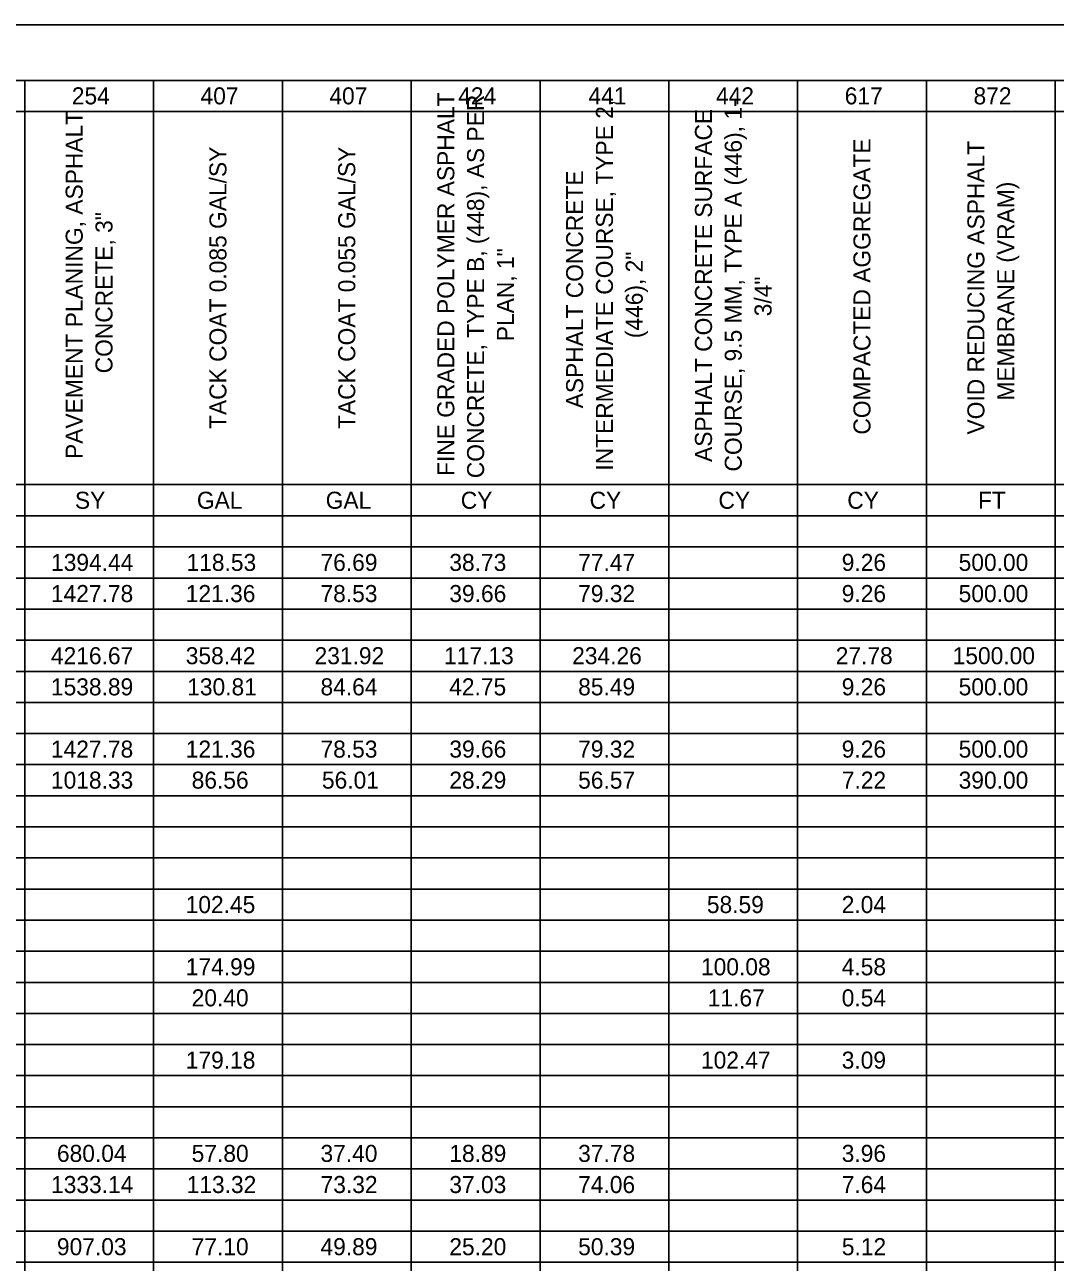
# Model space of a CAD drawing. Extents: x 0 to 34, y 0 to 22.
# Drawn here: x 16.38 to 25.65, y 10.87 to 22 of the extents above; entities that cross this region are included whole.
import ezdxf

# ---------------------------------------------------------------- set-up
doc = ezdxf.new("R2010")
doc.units = 0
for name, color, linetype in [('SH_Border', 7, 'Continuous'), ('SH_Cut_Line', 7, 'Continuous'), ('SH_Text', 7, 'Continuous')]:
    doc.layers.add(name, color=color, linetype=linetype)

msp = doc.modelspace()

# ---------------------------------------------------------------- linework, layer by layer
at = {"layer": 'SH_Border'}
msp.add_lwpolyline([(1.5, 21.5), (33.5, 21.5), (33.5, 0.5), (1.5, 0.5)], close=True, dxfattribs=at)
at = {"layer": 'SH_Cut_Line'}
msp.add_lwpolyline([(0, 0), (34, 0), (34, 22), (0, 22)], close=True, dxfattribs=at)
at = {"layer": 'SH_Text'}
for p, q in [((15.22, 21.5), (16.378, 21.5)), ((16.378, 21.5), (24.49, 21.5)), ((16.378, 21.5), (16.378, 21.22)), ((17.537, 21.5), (17.537, 21.22)), ((18.696, 21.5), (18.696, 21.22)), ((19.855, 21.5), (19.855, 21.22)), ((21.014, 21.5), (21.014, 21.22)), ((22.173, 21.5), (22.173, 21.22)), ((23.331, 21.5), (23.331, 21.22)), ((24.49, 21.5), (25.649, 21.5)), ((24.49, 21.5), (24.49, 21.22)), ((25.649, 21.5), (27.967, 21.5)), ((25.649, 21.5), (25.649, 21.22)), ((15.22, 21.22), (16.378, 21.22)), ((16.378, 21.22), (24.49, 21.22)), ((16.378, 21.22), (16.378, 20.941)), ((17.537, 21.22), (17.537, 20.941)), ((18.696, 21.22), (18.696, 20.941)), ((19.855, 21.22), (19.855, 20.941)), ((21.014, 21.22), (21.014, 20.941)), ((22.173, 21.22), (22.173, 20.941)), ((23.331, 21.22), (23.331, 20.941)), ((24.49, 21.22), (25.649, 21.22)), ((24.49, 21.22), (24.49, 20.941)), ((25.649, 21.22), (27.967, 21.22)), ((25.649, 21.22), (25.649, 20.941)), ((16.378, 20.941), (16.378, 20.661)), ((17.537, 20.941), (17.537, 20.661)), ((18.696, 20.941), (18.696, 20.661)), ((19.855, 20.941), (19.855, 20.661)), ((21.014, 20.941), (21.014, 20.661)), ((22.173, 20.941), (22.173, 20.661)), ((23.331, 20.941), (23.331, 20.661)), ((24.49, 20.941), (24.49, 20.661)), ((25.649, 20.941), (25.649, 20.661)), ((16.378, 20.661), (16.378, 20.381)), ((17.537, 20.661), (17.537, 20.381)), ((18.696, 20.661), (18.696, 20.381)), ((19.855, 20.661), (19.855, 20.381)), ((21.014, 20.661), (21.014, 20.381)), ((22.173, 20.661), (22.173, 20.381)), ((23.331, 20.661), (23.331, 20.381)), ((24.49, 20.661), (24.49, 20.381)), ((25.649, 20.661), (25.649, 20.381)), ((16.378, 20.381), (16.378, 20.101)), ((17.537, 20.381), (17.537, 20.101)), ((18.696, 20.381), (18.696, 20.101)), ((19.855, 20.381), (19.855, 20.101)), ((21.014, 20.381), (21.014, 20.101)), ((22.173, 20.381), (22.173, 20.101)), ((23.331, 20.381), (23.331, 20.101)), ((24.49, 20.381), (24.49, 20.101)), ((25.649, 20.381), (25.649, 20.101)), ((16.378, 20.101), (16.378, 19.822)), ((17.537, 20.101), (17.537, 19.822)), ((18.696, 20.101), (18.696, 19.822)), ((19.855, 20.101), (19.855, 19.822)), ((21.014, 20.101), (21.014, 19.822)), ((22.173, 20.101), (22.173, 19.822)), ((23.331, 20.101), (23.331, 19.822)), ((24.49, 20.101), (24.49, 19.822)), ((25.649, 20.101), (25.649, 19.822)), ((16.378, 19.822), (16.378, 19.542)), ((17.537, 19.822), (17.537, 19.542)), ((18.696, 19.822), (18.696, 19.542)), ((19.855, 19.822), (19.855, 19.542)), ((21.014, 19.822), (21.014, 19.542)), ((22.173, 19.822), (22.173, 19.542)), ((23.331, 19.822), (23.331, 19.542)), ((24.49, 19.822), (24.49, 19.542)), ((25.649, 19.822), (25.649, 19.542)), ((16.378, 19.542), (16.378, 19.262)), ((17.537, 19.542), (17.537, 19.262)), ((18.696, 19.542), (18.696, 19.262)), ((19.855, 19.542), (19.855, 19.262)), ((21.014, 19.542), (21.014, 19.262)), ((22.173, 19.542), (22.173, 19.262)), ((23.331, 19.542), (23.331, 19.262)), ((24.49, 19.542), (24.49, 19.262)), ((25.649, 19.542), (25.649, 19.262)), ((16.378, 19.262), (16.378, 18.983)), ((17.537, 19.262), (17.537, 18.983)), ((18.696, 19.262), (18.696, 18.983)), ((19.855, 19.262), (19.855, 18.983)), ((21.014, 19.262), (21.014, 18.983)), ((22.173, 19.262), (22.173, 18.983)), ((23.331, 19.262), (23.331, 18.983)), ((24.49, 19.262), (24.49, 18.983)), ((25.649, 19.262), (25.649, 18.983)), ((16.378, 18.983), (16.378, 18.703)), ((17.537, 18.983), (17.537, 18.703)), ((18.696, 18.983), (18.696, 18.703)), ((19.855, 18.983), (19.855, 18.703)), ((21.014, 18.983), (21.014, 18.703)), ((22.173, 18.983), (22.173, 18.703)), ((23.331, 18.983), (23.331, 18.703)), ((24.49, 18.983), (24.49, 18.703)), ((25.649, 18.983), (25.649, 18.703)), ((16.378, 18.703), (16.378, 18.423)), ((17.537, 18.703), (17.537, 18.423)), ((18.696, 18.703), (18.696, 18.423)), ((19.855, 18.703), (19.855, 18.423)), ((21.014, 18.703), (21.014, 18.423)), ((22.173, 18.703), (22.173, 18.423)), ((23.331, 18.703), (23.331, 18.423)), ((24.49, 18.703), (24.49, 18.423)), ((25.649, 18.703), (25.649, 18.423)), ((16.378, 18.423), (16.378, 18.143)), ((17.537, 18.423), (17.537, 18.143)), ((18.696, 18.423), (18.696, 18.143)), ((19.855, 18.423), (19.855, 18.143)), ((21.014, 18.423), (21.014, 18.143)), ((22.173, 18.423), (22.173, 18.143)), ((23.331, 18.423), (23.331, 18.143)), ((24.49, 18.423), (24.49, 18.143)), ((25.649, 18.423), (25.649, 18.143)), ((16.378, 18.143), (16.378, 17.864)), ((17.537, 18.143), (17.537, 17.864)), ((18.696, 18.143), (18.696, 17.864)), ((19.855, 18.143), (19.855, 17.864)), ((21.014, 18.143), (21.014, 17.864)), ((22.173, 18.143), (22.173, 17.864)), ((23.331, 18.143), (23.331, 17.864)), ((24.49, 18.143), (24.49, 17.864)), ((25.649, 18.143), (25.649, 17.864)), ((15.22, 17.864), (16.378, 17.864)), ((16.378, 17.864), (24.49, 17.864)), ((16.378, 17.864), (16.378, 17.584)), ((17.537, 17.864), (17.537, 17.584)), ((18.696, 17.864), (18.696, 17.584)), ((19.855, 17.864), (19.855, 17.584)), ((21.014, 17.864), (21.014, 17.584)), ((22.173, 17.864), (22.173, 17.584)), ((23.331, 17.864), (23.331, 17.584)), ((24.49, 17.864), (25.649, 17.864)), ((24.49, 17.864), (24.49, 17.584)), ((25.649, 17.864), (27.967, 17.864)), ((25.649, 17.864), (25.649, 17.584)), ((15.22, 17.584), (16.378, 17.584)), ((16.378, 17.584), (24.49, 17.584)), ((16.378, 17.584), (16.378, 17.304)), ((17.537, 17.584), (17.537, 17.304)), ((18.696, 17.584), (18.696, 17.304)), ((19.855, 17.584), (19.855, 17.304)), ((21.014, 17.584), (21.014, 17.304)), ((22.173, 17.584), (22.173, 17.304)), ((23.331, 17.584), (23.331, 17.304)), ((24.49, 17.584), (25.649, 17.584)), ((24.49, 17.584), (24.49, 17.304)), ((25.649, 17.584), (27.967, 17.584)), ((25.649, 17.584), (25.649, 17.304)), ((15.22, 17.304), (16.378, 17.304)), ((16.378, 17.304), (24.49, 17.304)), ((16.378, 17.304), (16.378, 17.024)), ((17.537, 17.304), (17.537, 17.024)), ((18.696, 17.304), (18.696, 17.024)), ((19.855, 17.304), (19.855, 17.024)), ((21.014, 17.304), (21.014, 17.024)), ((22.173, 17.304), (22.173, 17.024)), ((23.331, 17.304), (23.331, 17.024)), ((24.49, 17.304), (25.649, 17.304)), ((24.49, 17.304), (24.49, 17.024)), ((25.649, 17.304), (27.967, 17.304)), ((25.649, 17.304), (25.649, 17.024)), ((15.22, 17.024), (16.378, 17.024)), ((16.378, 17.024), (24.49, 17.024)), ((16.378, 17.024), (16.378, 16.745)), ((17.537, 17.024), (17.537, 16.745)), ((18.696, 17.024), (18.696, 16.745)), ((19.855, 17.024), (19.855, 16.745)), ((21.014, 17.024), (21.014, 16.745)), ((22.173, 17.024), (22.173, 16.745)), ((23.331, 17.024), (23.331, 16.745)), ((24.49, 17.024), (25.649, 17.024)), ((24.49, 17.024), (24.49, 16.745)), ((25.649, 17.024), (27.967, 17.024)), ((25.649, 17.024), (25.649, 16.745)), ((15.22, 16.745), (16.378, 16.745)), ((16.378, 16.745), (24.49, 16.745)), ((16.378, 16.745), (16.378, 16.465)), ((17.537, 16.745), (17.537, 16.465)), ((18.696, 16.745), (18.696, 16.465)), ((19.855, 16.745), (19.855, 16.465)), ((21.014, 16.745), (21.014, 16.465)), ((22.173, 16.745), (22.173, 16.465)), ((23.331, 16.745), (23.331, 16.465)), ((24.49, 16.745), (25.649, 16.745)), ((24.49, 16.745), (24.49, 16.465)), ((25.649, 16.745), (27.967, 16.745)), ((25.649, 16.745), (25.649, 16.465)), ((15.22, 16.465), (16.378, 16.465)), ((16.378, 16.465), (24.49, 16.465)), ((16.378, 16.465), (16.378, 16.185)), ((17.537, 16.465), (17.537, 16.185)), ((18.696, 16.465), (18.696, 16.185)), ((19.855, 16.465), (19.855, 16.185)), ((21.014, 16.465), (21.014, 16.185)), ((22.173, 16.465), (22.173, 16.185)), ((23.331, 16.465), (23.331, 16.185)), ((24.49, 16.465), (25.649, 16.465)), ((24.49, 16.465), (24.49, 16.185)), ((25.649, 16.465), (27.967, 16.465)), ((25.649, 16.465), (25.649, 16.185)), ((15.22, 16.185), (16.378, 16.185)), ((16.378, 16.185), (24.49, 16.185)), ((16.378, 16.185), (16.378, 15.906)), ((17.537, 16.185), (17.537, 15.906)), ((18.696, 16.185), (18.696, 15.906)), ((19.855, 16.185), (19.855, 15.906)), ((21.014, 16.185), (21.014, 15.906)), ((22.173, 16.185), (22.173, 15.906)), ((23.331, 16.185), (23.331, 15.906)), ((24.49, 16.185), (25.649, 16.185)), ((24.49, 16.185), (24.49, 15.906)), ((25.649, 16.185), (27.967, 16.185)), ((25.649, 16.185), (25.649, 15.906)), ((15.22, 15.906), (16.378, 15.906)), ((16.378, 15.906), (24.49, 15.906)), ((16.378, 15.906), (16.378, 15.626)), ((17.537, 15.906), (17.537, 15.626)), ((18.696, 15.906), (18.696, 15.626)), ((19.855, 15.906), (19.855, 15.626)), ((21.014, 15.906), (21.014, 15.626)), ((22.173, 15.906), (22.173, 15.626)), ((23.331, 15.906), (23.331, 15.626)), ((24.49, 15.906), (25.649, 15.906)), ((24.49, 15.906), (24.49, 15.626)), ((25.649, 15.906), (27.967, 15.906)), ((25.649, 15.906), (25.649, 15.626)), ((15.22, 15.626), (16.378, 15.626)), ((16.378, 15.626), (24.49, 15.626)), ((16.378, 15.626), (16.378, 15.346)), ((17.537, 15.626), (17.537, 15.346)), ((18.696, 15.626), (18.696, 15.346)), ((19.855, 15.626), (19.855, 15.346)), ((21.014, 15.626), (21.014, 15.346)), ((22.173, 15.626), (22.173, 15.346)), ((23.331, 15.626), (23.331, 15.346)), ((24.49, 15.626), (25.649, 15.626)), ((24.49, 15.626), (24.49, 15.346)), ((25.649, 15.626), (27.967, 15.626)), ((25.649, 15.626), (25.649, 15.346)), ((15.22, 15.346), (16.378, 15.346)), ((16.378, 15.346), (24.49, 15.346)), ((16.378, 15.346), (16.378, 15.066)), ((17.537, 15.346), (17.537, 15.066)), ((18.696, 15.346), (18.696, 15.066)), ((19.855, 15.346), (19.855, 15.066)), ((21.014, 15.346), (21.014, 15.066)), ((22.173, 15.346), (22.173, 15.066)), ((23.331, 15.346), (23.331, 15.066)), ((24.49, 15.346), (25.649, 15.346)), ((24.49, 15.346), (24.49, 15.066)), ((25.649, 15.346), (27.967, 15.346)), ((25.649, 15.346), (25.649, 15.066)), ((15.22, 15.066), (16.378, 15.066)), ((16.378, 15.066), (24.49, 15.066)), ((16.378, 15.066), (16.378, 14.787)), ((17.537, 15.066), (17.537, 14.787)), ((18.696, 15.066), (18.696, 14.787)), ((19.855, 15.066), (19.855, 14.787)), ((21.014, 15.066), (21.014, 14.787)), ((22.173, 15.066), (22.173, 14.787)), ((23.331, 15.066), (23.331, 14.787)), ((24.49, 15.066), (25.649, 15.066)), ((24.49, 15.066), (24.49, 14.787)), ((25.649, 15.066), (27.967, 15.066)), ((25.649, 15.066), (25.649, 14.787)), ((15.22, 14.787), (16.378, 14.787)), ((16.378, 14.787), (24.49, 14.787)), ((16.378, 14.787), (16.378, 14.507)), ((17.537, 14.787), (17.537, 14.507)), ((18.696, 14.787), (18.696, 14.507)), ((19.855, 14.787), (19.855, 14.507)), ((21.014, 14.787), (21.014, 14.507)), ((22.173, 14.787), (22.173, 14.507)), ((23.331, 14.787), (23.331, 14.507)), ((24.49, 14.787), (25.649, 14.787)), ((24.49, 14.787), (24.49, 14.507)), ((25.649, 14.787), (27.967, 14.787)), ((25.649, 14.787), (25.649, 14.507)), ((15.22, 14.507), (16.378, 14.507)), ((16.378, 14.507), (24.49, 14.507)), ((16.378, 14.507), (16.378, 14.227)), ((17.537, 14.507), (17.537, 14.227)), ((18.696, 14.507), (18.696, 14.227)), ((19.855, 14.507), (19.855, 14.227)), ((21.014, 14.507), (21.014, 14.227)), ((22.173, 14.507), (22.173, 14.227)), ((23.331, 14.507), (23.331, 14.227)), ((24.49, 14.507), (25.649, 14.507)), ((24.49, 14.507), (24.49, 14.227)), ((25.649, 14.507), (27.967, 14.507)), ((25.649, 14.507), (25.649, 14.227)), ((15.22, 14.227), (16.378, 14.227)), ((16.378, 14.227), (24.49, 14.227)), ((16.378, 14.227), (16.378, 13.948)), ((17.537, 14.227), (17.537, 13.948)), ((18.696, 14.227), (18.696, 13.948)), ((19.855, 14.227), (19.855, 13.948)), ((21.014, 14.227), (21.014, 13.948)), ((22.173, 14.227), (22.173, 13.948)), ((23.331, 14.227), (23.331, 13.948)), ((24.49, 14.227), (25.649, 14.227)), ((24.49, 14.227), (24.49, 13.948)), ((25.649, 14.227), (27.967, 14.227)), ((25.649, 14.227), (25.649, 13.948)), ((15.22, 13.948), (16.378, 13.948)), ((16.378, 13.948), (24.49, 13.948)), ((16.378, 13.948), (16.378, 13.668)), ((17.537, 13.948), (17.537, 13.668)), ((18.696, 13.948), (18.696, 13.668)), ((19.855, 13.948), (19.855, 13.668)), ((21.014, 13.948), (21.014, 13.668)), ((22.173, 13.948), (22.173, 13.668)), ((23.331, 13.948), (23.331, 13.668)), ((24.49, 13.948), (25.649, 13.948)), ((24.49, 13.948), (24.49, 13.668)), ((25.649, 13.948), (27.967, 13.948)), ((25.649, 13.948), (25.649, 13.668)), ((15.22, 13.668), (16.378, 13.668)), ((16.378, 13.668), (24.49, 13.668)), ((16.378, 13.668), (16.378, 13.388)), ((17.537, 13.668), (17.537, 13.388)), ((18.696, 13.668), (18.696, 13.388)), ((19.855, 13.668), (19.855, 13.388)), ((21.014, 13.668), (21.014, 13.388)), ((22.173, 13.668), (22.173, 13.388)), ((23.331, 13.668), (23.331, 13.388)), ((24.49, 13.668), (25.649, 13.668)), ((24.49, 13.668), (24.49, 13.388)), ((25.649, 13.668), (27.967, 13.668)), ((25.649, 13.668), (25.649, 13.388)), ((15.22, 13.388), (16.378, 13.388)), ((16.378, 13.388), (24.49, 13.388)), ((16.378, 13.388), (16.378, 13.108)), ((17.537, 13.388), (17.537, 13.108)), ((18.696, 13.388), (18.696, 13.108)), ((19.855, 13.388), (19.855, 13.108)), ((21.014, 13.388), (21.014, 13.108)), ((22.173, 13.388), (22.173, 13.108)), ((23.331, 13.388), (23.331, 13.108)), ((24.49, 13.388), (25.649, 13.388)), ((24.49, 13.388), (24.49, 13.108)), ((25.649, 13.388), (27.967, 13.388)), ((25.649, 13.388), (25.649, 13.108)), ((15.22, 13.108), (16.378, 13.108)), ((16.378, 13.108), (24.49, 13.108)), ((16.378, 13.108), (16.378, 12.829)), ((17.537, 13.108), (17.537, 12.829)), ((18.696, 13.108), (18.696, 12.829)), ((19.855, 13.108), (19.855, 12.829)), ((21.014, 13.108), (21.014, 12.829)), ((22.173, 13.108), (22.173, 12.829)), ((23.331, 13.108), (23.331, 12.829)), ((24.49, 13.108), (25.649, 13.108)), ((24.49, 13.108), (24.49, 12.829)), ((25.649, 13.108), (27.967, 13.108)), ((25.649, 13.108), (25.649, 12.829)), ((15.22, 12.829), (16.378, 12.829)), ((16.378, 12.829), (24.49, 12.829)), ((16.378, 12.829), (16.378, 12.549)), ((17.537, 12.829), (17.537, 12.549)), ((18.696, 12.829), (18.696, 12.549)), ((19.855, 12.829), (19.855, 12.549)), ((21.014, 12.829), (21.014, 12.549)), ((22.173, 12.829), (22.173, 12.549)), ((23.331, 12.829), (23.331, 12.549)), ((24.49, 12.829), (25.649, 12.829)), ((24.49, 12.829), (24.49, 12.549)), ((25.649, 12.829), (27.967, 12.829)), ((25.649, 12.829), (25.649, 12.549)), ((15.22, 12.549), (16.378, 12.549)), ((16.378, 12.549), (24.49, 12.549)), ((16.378, 12.549), (16.378, 12.269)), ((17.537, 12.549), (17.537, 12.269)), ((18.696, 12.549), (18.696, 12.269)), ((19.855, 12.549), (19.855, 12.269)), ((21.014, 12.549), (21.014, 12.269)), ((22.173, 12.549), (22.173, 12.269)), ((23.331, 12.549), (23.331, 12.269)), ((24.49, 12.549), (25.649, 12.549)), ((24.49, 12.549), (24.49, 12.269)), ((25.649, 12.549), (27.967, 12.549)), ((25.649, 12.549), (25.649, 12.269)), ((15.22, 12.269), (16.378, 12.269)), ((16.378, 12.269), (24.49, 12.269)), ((16.378, 12.269), (16.378, 11.99)), ((17.537, 12.269), (17.537, 11.99)), ((18.696, 12.269), (18.696, 11.99)), ((19.855, 12.269), (19.855, 11.99)), ((21.014, 12.269), (21.014, 11.99)), ((22.173, 12.269), (22.173, 11.99)), ((23.331, 12.269), (23.331, 11.99)), ((24.49, 12.269), (25.649, 12.269)), ((24.49, 12.269), (24.49, 11.99)), ((25.649, 12.269), (27.967, 12.269)), ((25.649, 12.269), (25.649, 11.99)), ((15.22, 11.99), (16.378, 11.99)), ((16.378, 11.99), (24.49, 11.99)), ((16.378, 11.99), (16.378, 11.71)), ((17.537, 11.99), (17.537, 11.71)), ((18.696, 11.99), (18.696, 11.71)), ((19.855, 11.99), (19.855, 11.71)), ((21.014, 11.99), (21.014, 11.71)), ((22.173, 11.99), (22.173, 11.71)), ((23.331, 11.99), (23.331, 11.71)), ((24.49, 11.99), (25.649, 11.99)), ((24.49, 11.99), (24.49, 11.71)), ((25.649, 11.99), (27.967, 11.99)), ((25.649, 11.99), (25.649, 11.71)), ((15.22, 11.71), (16.378, 11.71)), ((16.378, 11.71), (24.49, 11.71)), ((16.378, 11.71), (16.378, 11.43)), ((17.537, 11.71), (17.537, 11.43)), ((18.696, 11.71), (18.696, 11.43)), ((19.855, 11.71), (19.855, 11.43)), ((21.014, 11.71), (21.014, 11.43)), ((22.173, 11.71), (22.173, 11.43)), ((23.331, 11.71), (23.331, 11.43)), ((24.49, 11.71), (25.649, 11.71)), ((24.49, 11.71), (24.49, 11.43)), ((25.649, 11.71), (27.967, 11.71)), ((25.649, 11.71), (25.649, 11.43)), ((15.22, 11.43), (16.378, 11.43)), ((16.378, 11.43), (24.49, 11.43)), ((16.378, 11.43), (16.378, 11.15)), ((17.537, 11.43), (17.537, 11.15)), ((18.696, 11.43), (18.696, 11.15)), ((19.855, 11.43), (19.855, 11.15)), ((21.014, 11.43), (21.014, 11.15)), ((22.173, 11.43), (22.173, 11.15)), ((23.331, 11.43), (23.331, 11.15)), ((24.49, 11.43), (25.649, 11.43)), ((24.49, 11.43), (24.49, 11.15)), ((25.649, 11.43), (27.967, 11.43)), ((25.649, 11.43), (25.649, 11.15)), ((15.22, 11.15), (16.378, 11.15)), ((16.378, 11.15), (24.49, 11.15)), ((16.378, 11.15), (16.378, 10.871)), ((17.537, 11.15), (17.537, 10.871)), ((18.696, 11.15), (18.696, 10.871)), ((19.855, 11.15), (19.855, 10.871)), ((21.014, 11.15), (21.014, 10.871)), ((22.173, 11.15), (22.173, 10.871)), ((23.331, 11.15), (23.331, 10.871)), ((24.49, 11.15), (25.649, 11.15)), ((24.49, 11.15), (24.49, 10.871)), ((25.649, 11.15), (27.967, 11.15)), ((25.649, 11.15), (25.649, 10.871)), ((15.22, 10.871), (16.378, 10.871)), ((16.378, 10.871), (24.49, 10.871)), ((16.378, 10.871), (16.378, 10.591)), ((17.537, 10.871), (17.537, 10.591)), ((18.696, 10.871), (18.696, 10.591)), ((19.855, 10.871), (19.855, 10.591)), ((21.014, 10.871), (21.014, 10.591)), ((22.173, 10.871), (22.173, 10.591)), ((23.331, 10.871), (23.331, 10.591)), ((24.49, 10.871), (25.649, 10.871)), ((24.49, 10.871), (24.49, 10.591)), ((25.649, 10.871), (27.967, 10.871)), ((25.649, 10.871), (25.649, 10.591))]:
    msp.add_line(p, q, dxfattribs=at)

# ---------------------------------------------------------------- texts
for s, p in [('254', (16.802, 21.284)), ('407', (17.96, 21.284)), ('407', (19.119, 21.284)), ('424', (20.278, 21.284)), ('441', (21.45, 21.284)), ('442', (22.597, 21.284)), ('617', (23.755, 21.284)), ('872', (24.914, 21.284)), ('SY', (16.83, 17.647)), ('GAL', (17.927, 17.647)), ('GAL', (19.086, 17.647)), ('CY', (20.301, 17.647)), ('CY', (21.46, 17.647)), ('CY', (22.619, 17.647)), ('CY', (23.778, 17.647)), ('FT', (24.954, 17.647)), ('1394.44', (16.615, 17.088)), ('118.53', (17.834, 17.088)), ('76.69', (19.039, 17.088)), ('38.73', (20.198, 17.088)), ('77.47', (21.357, 17.088)), ('9.26', (23.728, 17.088)), ('500.00', (24.78, 17.088)), ('1427.78', (16.614, 16.808)), ('121.36', (17.827, 16.808)), ('78.53', (19.039, 16.808)), ('39.66', (20.198, 16.808)), ('79.32', (21.357, 16.808)), ('9.26', (23.728, 16.808)), ('500.00', (24.78, 16.808)), ('4216.67', (16.614, 16.249)), ('358.42', (17.827, 16.249)), ('231.92', (18.986, 16.249)), ('117.13', (20.151, 16.249)), ('234.26', (21.303, 16.249)), ('27.78', (23.674, 16.249)), ('1500.00', (24.726, 16.249)), ('1538.89', (16.614, 15.969)), ('130.81', (17.84, 15.969)), ('84.64', (19.039, 15.969)), ('42.75', (20.197, 15.969)), ('85.49', (21.357, 15.969)), ('9.26', (23.728, 15.969)), ('500.00', (24.78, 15.969)), ('1427.78', (16.614, 15.409)), ('121.36', (17.827, 15.409)), ('78.53', (19.039, 15.409)), ('39.66', (20.198, 15.409)), ('79.32', (21.357, 15.409)), ('9.26', (23.728, 15.409)), ('500.00', (24.78, 15.409)), ('1018.33', (16.614, 15.13)), ('86.56', (17.88, 15.13)), ('56.01', (19.052, 15.13)), ('28.29', (20.198, 15.13)), ('56.57', (21.357, 15.13)), ('7.22', (23.729, 15.13)), ('390.00', (24.78, 15.13)), ('102.45', (17.826, 14.011)), ('58.59', (22.515, 14.011)), ('2.04', (23.728, 14.011)), ('174.99', (17.827, 13.451)), ('100.08', (22.462, 13.451)), ('4.58', (23.728, 13.451)), ('20.40', (17.88, 13.172)), ('11.67', (22.523, 13.172)), ('0.54', (23.728, 13.172)), ('179.18', (17.827, 12.612)), ('102.47', (22.462, 12.612)), ('3.09', (23.728, 12.612)), ('680.04', (16.668, 11.773)), ('57.80', (17.88, 11.773)), ('37.40', (19.039, 11.773)), ('18.89', (20.198, 11.773)), ('37.78', (21.357, 11.773)), ('3.96', (23.728, 11.773)), ('1333.14', (16.615, 11.493)), ('113.32', (17.835, 11.493)), ('73.32', (19.04, 11.493)), ('37.03', (20.198, 11.493)), ('74.06', (21.357, 11.493)), ('7.64', (23.728, 11.493)), ('907.03', (16.668, 10.934)), ('77.10', (17.88, 10.934)), ('49.89', (19.039, 10.934)), ('25.20', (20.198, 10.934)), ('50.39', (21.357, 10.934)), ('5.12', (23.729, 10.934))]:
    msp.add_text(s, height=0.1532, dxfattribs=at).set_placement(p)
for s, height, p in [('FINE GRADED POLYMER ASPHALT ', 0.15318, (20.243, 17.942)), ('CONCRETE, TYPE B, (448), AS PER ', 0.15318, (20.511, 17.922)), ('INTERMEDIATE COURSE, TYPE 2, ', 0.15318, (21.67, 17.99)), ('COURSE, 9.5 MM, TYPE A (446), 1-', 0.15318, (22.829, 17.982)), ('PAVEMENT PLANING, ASPHALT ', 0.15318, (16.9, 18.095)), ('ASPHALT CONCRETE SURFACE ', 0.15318, (22.561, 18.068)), ('COMPACTED AGGREGATE', 0.15318, (23.987, 18.314)), ('VOID REDUCING ASPHALT ', 0.15318, (25.012, 18.315)), ('TACK COAT 0.085 GAL/SY', 0.15318, (18.193, 18.365)), ('TACK COAT 0.055 GAL/SY', 0.15318, (19.352, 18.365)), ('ASPHALT CONCRETE ', 0.15318, (21.402, 18.55)), ('MEMBRANE (VRAM)', 0.15318, (25.28, 18.62)), ('CONCRETE, 3"', 0.15318, (17.168, 18.865)), ('PLAN, 1"', 0.1532, (20.779, 19.154)), ('(446), 2"', 0.1532, (21.938, 19.181)), ('3/4"', 0.1532, (23.097, 19.378))]:
    msp.add_text(s, height=height, rotation=90, dxfattribs=at).set_placement(p)

doc.saveas('drawing.dxf')
